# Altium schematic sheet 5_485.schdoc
size 309 x 223 mm; Symbol: Sheet-Symbol_A4; Device: Sheet-Symbol_A4; Company: 嘉立创EDA; Version: V1.0; Page Size: A4; @Project Name: 共享电动车中控; @Page Count: 11; @Update Date: 2024-11-20; @Create Date: 2024-09-26; @Schematic Name: SCH; @Page No: 5; @Page Name: 485; @Board Name: STM32F103C8T6; @Create Time: 02:39:01; @Update Time: 15:21:40
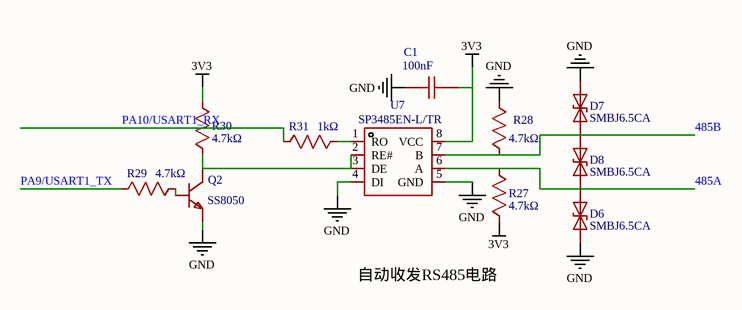
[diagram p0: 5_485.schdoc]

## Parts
C1  100nF  [C0805]  (value not drawn)
D6  SMBJ6.5CA  [SMB_L4.6-W3.5-LS5.3-BI]  (value not drawn)
D7  SMBJ6.5CA  [SMB_L4.6-W3.5-LS5.3-BI]  (value not drawn)
D8  SMBJ6.5CA  [SMB_L4.6-W3.5-LS5.3-BI]  (value not drawn)
Q2  SS8050  [SOT-23-3_L2.9-W1.3-P1.90-LS2.4-BR]  (value not drawn)
R27  4.7kΩ  [R0805]  (value not drawn)
R28  4.7kΩ  [R0805]  (value not drawn)
R29  4.7kΩ  [R0805]  (value not drawn)
R30  4.7kΩ  [R0805]  (value not drawn)
R31  1kΩ  [R0805]  (value not drawn)
U7  SP3485EN-L/TR  [SOIC-8_L5.0-W4.0-P1.27-LS6.0-BL]  (value not drawn)

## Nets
3V3: C1.1 R27.1 R30.2 U7.8(VCC)
GND: C1.2 D6.2(A) D7.1(K) Q2.2(E) R28.2 U7.4(DI) U7.5(GND)
485A: D6.1(K) D8.2(A) R27.2 U7.6(A)
485B: D7.2(A) D8.1(K) R28.1 U7.7(B)
PA9/USART1_TX: R29.1
PA10/USART1_RX: R31.1
NetQ2_1: Q2.1(B) R29.2
NetQ2_3: Q2.3(C) R30.1 U7.2(RE#) U7.3(DE)
NetR31_2: R31.2 U7.1(RO)

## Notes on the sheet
- 自动收发RS485电路

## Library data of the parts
C1 = CC0805KRX7R9BB104: 容值:100nF;精度:±10%;额定电压:50V;材质(温度系数):X7R;; Manufacturer: YAGEO(国巨); Symbol: 0.1uF; Add into BOM: yes; Tolerance: ±10%; Voltage Rated: 50V; Temperature Coefficient: X7R; Origin Footprint: 0603
D6-D8 = SMBJ6.5CA_C7420377: 极性:双向;反向截止电压(Vrwm):6.5V;最大钳位电压:11.2V;峰值脉冲电流(Ipp)@10/1000us:53.57A;峰值脉冲功率(Ppp)@10/1000us:600W;击穿电压:7.22V;; Manufacturer: 宏迦橙; Add into BOM: yes; polarity: 双向; Reverse Stand-Off Voltage (Vrwm): 6.5V; Maximum Clamping Voltage: 11.2V; Peak Pulse Current (Ipp)@10/1000us: 53.57A; Peak Pulse Power Dissipation (Ppp)@10/1000us: 600W; Breakdown Voltage: 7.22V; Reverse Leakage Current (Ir): 500uA; Number of Lines: 单路; Type: TVS; Origin Footprint: SMB_L4.6-W3.6-LS5.3-BI
Q2 = SS8050_C7420370: 晶体管类型:NPN;集电极电流(Ic):1.5A;集射极击穿电压(Vceo):25V;功率(Pd):300mW;直流电流增益(hFE@Ic,Vce):120@100mA,1.0V;; Manufacturer: 宏迦橙; Add into BOM: yes; Transistor Type: NPN; Collector Current (Ic): 1.5A; Collector-Emitter Breakdown Voltage (Vceo): 25V; Power Dissipation (Pd): 300mW; Transition Frequency (fT): 100MHz; Collector Cut-Off Current (Icbo): 100nA; Collector-Emitter Saturation Voltage (VCE(sat)@Ic,Ib): 500mV@800mA,80mA
R27-R30 = 0805W8F4701T5E: 电阻类型:厚膜电阻;阻值:4.7kΩ;精度:±1%;功率:125mW;最大工作电压:150V;温度系数:±100ppm/℃;; Manufacturer: UNI-ROYAL(厚声); Symbol: 4.7k; Add into BOM: yes; Tolerance: ±1%; Power(Watts): 125mW; Overload Voltage (Max): 150V; Origin Footprint: R0603
R31 = 0805W8F1001T5E: 电阻类型:厚膜电阻;阻值:1kΩ;精度:±1%;功率:125mW;最大工作电压:150V;温度系数:±100ppm/℃;; Manufacturer: UNI-ROYAL(厚声); Symbol: 1k; Add into BOM: yes; Tolerance: ±1%; Power(Watts): 125mW; Overload Voltage (Max): 150V; Origin Footprint: R0603
U7 = SP3485EN-L/TR: Manufacturer: EXAR; Convert to PCB: yes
